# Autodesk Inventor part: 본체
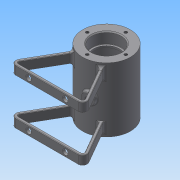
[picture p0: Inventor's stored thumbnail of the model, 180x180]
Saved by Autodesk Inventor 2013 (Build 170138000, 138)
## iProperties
Created: 2016-03
Part Number: 본체
Material: Generic
Document SubType Name: Modeling
Designer: Administrator
Density: 1 g/cm^3
Author: Administrator
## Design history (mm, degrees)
sketch "스케치1"
  geometry: C1 r 26 at (0, 0); 1 further point
  constraints: 1 centre point, 1 coincident
  dimensions: "d0" = 52 diameter of C1
extrude "돌출1" new body sketch "스케치1" stored distance "d1" = 70; taper "d2" = 0 deg
node "작업 평면1"
sketch "스케치2"
  geometry: L1 (0, 0)-(0, -65); L2 (-42.594, -65)-(42.594, -65); L3 (42.594, -65)-(0, 8.775); L4 (42.594, -65)-(94.556, -65); L5 (-42.594, -65)-(0, 8.775); C1 r 26 at (0, 0) reference
  constraints: 10 end point, 1 horizontal, 1 midpoint, 1 perpendicular, 1 vertical, 1 other
  dimensions: "d4" = 65 distance of L1.end L1.start; "d5" = 120 deg angle of L4 L3; "d7" = 85.18802 distance of L2.start L2.end
feature "리브1" sketch "스케치2" dims "d8" = 3, "d9" = 10, "d10" = 0, "d11" = 0, "d12" = 1, "d13" = 1
fillet "모깎기1" dims "d14" = 5
fillet "모깎기2" dims "d15" = 2
sketch "스케치3"
  geometry: C1 r 21 at (0, 0); 1 further point
  constraints: 1 centre point, 1 coincident
  dimensions: "d16" = 42 diameter of C1
extrude "돌출2" cut sketch "스케치3" stored distance "d17" = 42; taper "d18" = 0 deg
hole "구멍1" diameter "d21" = 28; stored, may be unused: countersink angle "d25" = 90 deg, drill point angle "d27" = 118 deg; dims "d19" = 10, "d20" = 10, "d22" = 6, "d23" = 32, "d24" = 12, "d26" = 8
sketch "스케치4"
  geometry: C1 r 14 at (0, 0) reference; C2 r 26 at (0, 0) reference; C3 r 16 at (0, 0)
  constraints: 1 centre point, 1 coincident
  dimensions: "d28" = 32 diameter of C3
extrude "돌출3" cut sketch "스케치4" distance "d29" = 12; taper "d30" = 0 deg
fillet "모깎기3" dims "d31" = 3
fillet "모깎기4" dims "d32" = 0.3
fillet "모깎기5" dims "d33" = 3
fillet "모깎기6" dims "d34" = 3
fillet "모깎기7" dims "d35" = 0.5
node "작업 평면2"
sketch "스케치5"
  geometry: C1 r 5 at (0, 0); 1 further point
  constraints: 1 centre point, 1 coincident
  dimensions: "d37" = 10 diameter of C1
extrude "돌출4" join sketch "스케치5" stored distance "d38" = 12; taper "d39" = 0 deg
sketch "스케치6"
  geometry: C1 r 5 at (0, 0) reference; 1 further point
  constraints: 1 coincident
hole "구멍2" sketch "스케치6" at (0, 0) diameter "d40" = 5.188; stored, may be unused: countersink angle "d44" = 90 deg, drill point angle "d46" = 118 deg; dims "d41" = 6, "d42" = 32, "d43" = 12, "d45" = 8
fillet "모깎기8" dims "d47" = 2
sketch "스케치7"
  geometry: L1 (0, 0)-(7.506, -28.012); L2 (0, 0)-(29, 0)
  constraints: 4 end point, 1 equal length, 1 horizontal
  dimensions: "d48" = 29 distance of L1.start L1.end; "d49" = 75 deg angle of L1 L2
node "작업 평면3"
sketch "스케치8"
  geometry: C1 r 6 at (0, 0); 1 further point
  constraints: 1 centre point, 1 coincident
  dimensions: "d50" = 12 diameter of C1
extrude "돌출5" join sketch "스케치8" stored distance "d51" = 12; taper "d52" = 0 deg
hole "구멍3" diameter "d55" = 5.188; stored, may be unused: countersink angle "d59" = 90 deg, drill point angle "d61" = 118 deg; dims "d53" = 10, "d54" = 10, "d56" = 6, "d57" = 32, "d58" = 12, "d60" = 8
fillet "모깎기9" dims "d62" = 2
chamfer "모따기1" distance "d63" = 1; stored, may be unused: second distance "d64" = 2, angle "d65" = 45 deg
sketch "스케치9"
  geometry: C1 r 26 at (0, 0) reference; 1 further point
  constraints: 1 vertical alignment
  dimensions: "d66" = 21 distance of C1.centre point (0, 21)
hole "구멍4" sketch "스케치9" at (0, 21) diameter "d67" = 3.242; stored, may be unused: countersink angle "d71" = 90 deg, drill point angle "d73" = 118 deg; dims "d68" = 8, "d69" = 32, "d70" = 12, "d72" = 10
node "작업 평면4"
sketch "스케치10"
  geometry: 2 further points
  constraints: 1 coincident, 1 other
feature "엠보싱1" sketch "스케치10" dims "d15" = 2, "d77" = 0.5, "d78" = 0
sketch "스케치11"
  geometry: L1 (0, 0)-(0, 9) reference; L2 (0, -50)-(67.868, -50) reference; L3 (0, -41)-(0, -50) reference; L4 (67.868, -41)-(0, -41) reference; L5 (67.868, -50)-(67.868, -41) reference; 7 further points
  constraints: 4 horizontal alignment, 2 midpoint
  dimensions: "d79" = 20 horizontal distance of point (33.934, -20.5) point (13.934, -45.5); "d80" = 20 horizontal distance of point (53.934, -45.5) point (33.934, -20.5); "d81" = 20 horizontal distance of point (53.934, 4.5) point (33.934, -20.5); "d82" = 20 horizontal distance of point (13.934, 4.5) point (33.934, -20.5)
hole "구멍5" sketch "스케치11" at (13.934, 4.5), (53.934, 4.5), (13.934, -45.5), (53.934, -45.5) diameter "d83" = 6; stored, may be unused: countersink angle "d87" = 90 deg, drill point angle "d89" = 118 deg; dims "d84" = 8, "d85" = 32, "d86" = 12, "d88" = 10
node "솔리드1"
mirror "대칭1"
pattern_circular "원형 패턴1" dims angle "d75" = 360 deg
mirror "대칭2"
node "투영된 루프1"
node "투영된 루프2"
other parameters: "d3" = 25, "d36" = 29
